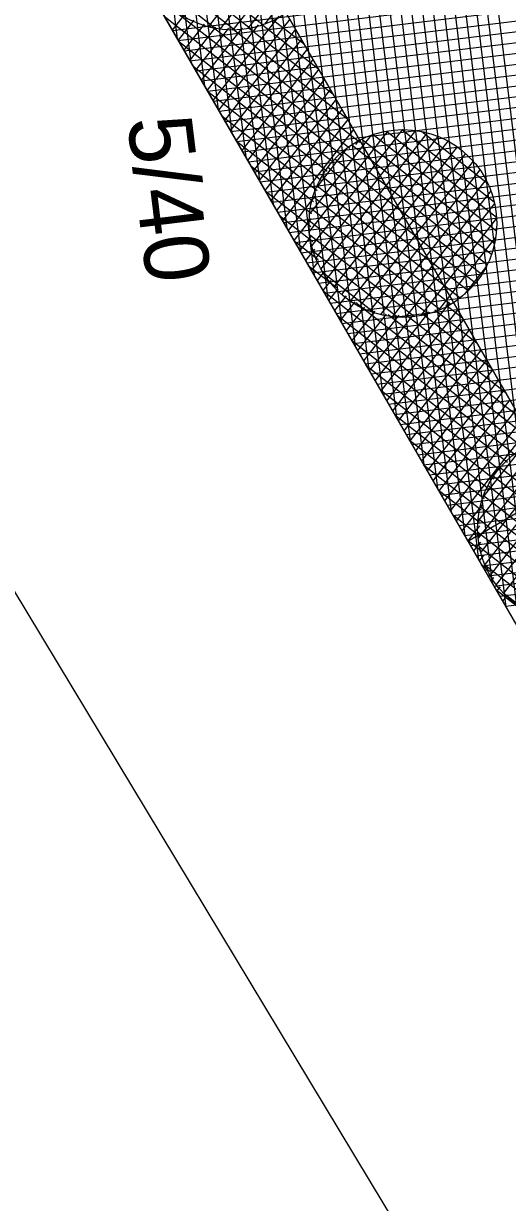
# Model space of a CAD drawing. Extents: x -566982 to -566809, y -1095912 to -1095685.
# Drawn here: x -566913.58 to -566904.55, y -1095817.35 to -1095795.39 of the extents above; entities that cross this region are included whole.
import ezdxf

# ---------------------------------------------------------------- set-up
doc = ezdxf.new("R2010")
doc.units = 0
for name, color, linetype in [('Vrstva 1', 7, 'Continuous'), ('Vrstva 40', 7, 'Continuous'), ('Vrstva 41', 7, 'Continuous'), ('Vrstva 42', 7, 'Continuous'), ('Vrstva 43', 7, 'Continuous'), ('Vrstva 44', 7, 'Continuous')]:
    doc.layers.add(name, color=color, linetype=linetype)

msp = doc.modelspace()

# ---------------------------------------------------------------- linework, layer by layer
at = {"layer": 'Vrstva 1'}
for p, q in [((-566956.66, -1095716.28), (-566892.27, -1095827.53)), ((-566928.71, -1095781.18), (-566901.69, -1095825.95))]:
    msp.add_line(p, q, dxfattribs=at)
at = {"layer": 'Vrstva 41'}
for p, q in [((-566911.222, -1095794.786), (-566907.49, -1095797.706)), ((-566910.953, -1095795.25), (-566907.651, -1095797.834)), ((-566910.581, -1095795.226), (-566910.803, -1095795.51)), ((-566908.819, -1095795.246), (-566910.047, -1095796.816)), ((-566908.611, -1095795.304), (-566909.939, -1095797.002)), ((-566910.402, -1095795.322), (-566910.695, -1095795.696)), ((-566910.208, -1095795.398), (-566910.587, -1095795.883)), ((-566909.995, -1095795.451), (-566910.479, -1095796.069)), ((-566909.758, -1095795.473), (-566910.371, -1095796.256)), ((-566909.501, -1095795.468), (-566910.263, -1095796.442)), ((-566909.2, -1095795.408), (-566910.155, -1095796.629)), ((-566910.067, -1095795.435), (-566907.307, -1095797.595)), ((-566908.503, -1095795.491), (-566909.831, -1095797.189)), ((-566909.696, -1095795.472), (-566907.535, -1095797.163)), ((-566909.395, -1095795.453), (-566907.804, -1095796.698)), ((-566909.147, -1095795.393), (-566908.073, -1095796.234)), ((-566908.933, -1095795.307), (-566908.341, -1095795.77)), ((-566910.685, -1095795.714), (-566907.793, -1095797.976)), ((-566908.395, -1095795.678), (-566909.723, -1095797.375)), ((-566908.287, -1095795.864), (-566909.615, -1095797.562)), ((-566910.416, -1095796.178), (-566907.916, -1095798.135)), ((-566908.179, -1095796.051), (-566909.507, -1095797.748)), ((-566908.071, -1095796.237), (-566909.399, -1095797.935)), ((-566907.963, -1095796.424), (-566909.291, -1095798.121)), ((-566907.855, -1095796.61), (-566909.183, -1095798.308)), ((-566910.147, -1095796.642), (-566908.02, -1095798.307)), ((-566907.747, -1095796.797), (-566909.075, -1095798.495)), ((-566907.639, -1095796.983), (-566908.967, -1095798.681)), ((-566909.879, -1095797.106), (-566908.104, -1095798.495)), ((-566907.531, -1095797.17), (-566908.859, -1095798.868)), ((-566907.423, -1095797.357), (-566908.751, -1095799.054)), ((-566909.61, -1095797.571), (-566908.168, -1095798.699)), ((-566907.315, -1095797.543), (-566907.39, -1095797.639)), ((-566909.341, -1095798.035), (-566908.209, -1095798.921)), ((-566909.073, -1095798.499), (-566908.218, -1095799.168)), ((-566908.143, -1095798.601), (-566908.643, -1095799.241)), ((-566908.804, -1095798.963), (-566908.185, -1095799.447)), ((-566908.216, -1095799.019), (-566908.535, -1095799.427)), ((-566908.535, -1095799.427), (-566908.081, -1095799.783)), ((-566908.206, -1095799.331), (-566908.427, -1095799.614)), ((-566908.151, -1095799.586), (-566908.319, -1095799.8)), ((-566908.267, -1095799.891), (-566907.722, -1095800.318)), ((-566908.071, -1095799.808), (-566908.212, -1095799.987)), ((-566907.97, -1095800.003), (-566908.104, -1095800.174)), ((-566907.998, -1095800.356), (-566904.226, -1095803.307)), ((-566907.85, -1095800.174), (-566907.996, -1095800.36)), ((-566907.714, -1095800.325), (-566907.888, -1095800.547)), ((-566907.564, -1095800.458), (-566907.78, -1095800.733)), ((-566907.4, -1095800.572), (-566907.672, -1095800.92)), ((-566907.221, -1095800.669), (-566907.564, -1095801.106)), ((-566907.027, -1095800.745), (-566907.456, -1095801.293)), ((-566907.384, -1095800.583), (-566904.043, -1095803.197)), ((-566906.02, -1095800.756), (-566907.024, -1095802.039)), ((-566905.639, -1095800.593), (-566906.916, -1095802.226)), ((-566905.479, -1095800.714), (-566906.808, -1095802.412)), ((-566906.146, -1095800.789), (-566904.849, -1095801.804)), ((-566905.909, -1095800.72), (-566905.117, -1095801.34)), ((-566905.703, -1095800.628), (-566905.386, -1095800.876)), ((-566907.73, -1095800.82), (-566904.401, -1095803.424)), ((-566906.815, -1095800.798), (-566907.348, -1095801.479)), ((-566906.578, -1095800.82), (-566907.24, -1095801.666)), ((-566906.32, -1095800.815), (-566907.132, -1095801.853)), ((-566906.776, -1095800.804), (-566904.311, -1095802.733)), ((-566905.371, -1095800.901), (-566906.7, -1095802.599)), ((-566906.434, -1095800.817), (-566904.58, -1095802.268)), ((-566905.263, -1095801.088), (-566906.592, -1095802.785)), ((-566907.461, -1095801.284), (-566904.555, -1095803.557)), ((-566905.155, -1095801.274), (-566906.484, -1095802.972)), ((-566905.047, -1095801.461), (-566906.376, -1095803.158)), ((-566904.94, -1095801.647), (-566906.268, -1095803.345)), ((-566907.192, -1095801.748), (-566904.691, -1095803.706)), ((-566904.832, -1095801.834), (-566906.16, -1095803.532)), ((-566904.724, -1095802.02), (-566906.052, -1095803.718)), ((-566906.924, -1095802.212), (-566904.808, -1095803.868)), ((-566904.616, -1095802.207), (-566905.944, -1095803.905)), ((-566904.508, -1095802.393), (-566905.836, -1095804.091)), ((-566906.655, -1095802.676), (-566904.906, -1095804.045)), ((-566904.4, -1095802.58), (-566905.728, -1095804.278)), ((-566904.292, -1095802.767), (-566905.62, -1095804.464)), ((-566904.184, -1095802.953), (-566905.512, -1095804.651)), ((-566906.386, -1095803.141), (-566904.986, -1095804.236)), ((-566906.118, -1095803.605), (-566905.044, -1095804.445)), ((-566905.849, -1095804.069), (-566905.075, -1095804.674)), ((-566905.02, -1095804.346), (-566905.404, -1095804.837)), ((-566905.58, -1095804.533), (-566905.073, -1095804.93)), ((-566905.077, -1095804.744), (-566905.296, -1095805.024)), ((-566905.312, -1095804.997), (-566905.024, -1095805.222)), ((-566905.06, -1095805.047), (-566905.188, -1095805.211)), ((-566905.002, -1095805.297), (-566905.08, -1095805.397)), ((-566905.043, -1095805.461), (-566904.883, -1095805.586)), ((-566904.92, -1095805.517), (-566904.972, -1095805.584)), ((-566904.815, -1095805.707), (-566904.864, -1095805.77)), ((-566904.774, -1095805.926), (-566901.554, -1095808.446)), ((-566904.693, -1095805.876), (-566904.756, -1095805.957)), ((-566904.556, -1095806.025), (-566904.648, -1095806.143))]:
    msp.add_line(p, q, dxfattribs=at)
at = {"layer": 'Vrstva 42'}
msp.add_line((-566905.294, -1095805.027), (-566903.563, -1095804.025), dxfattribs=at)
msp.add_lwpolyline([(-566834.15, -1095760.69), (-566836.072, -1095760.136), (-566841.286, -1095779.189), (-566855.268, -1095796.126), (-566881.984, -1095814.851), (-566891.818, -1095824.318), (-566954.342, -1095716.292), (-566956.66, -1095716.28), (-566892.27, -1095827.53), (-566880.71, -1095816.4), (-566853.9, -1095797.61), (-566839.47, -1095780.13)], close=True, dxfattribs=at)
at = {"layer": 'Vrstva 43'}
for p, q in [((-566913.798, -1095770.37), (-566910.711, -1095795.668)), ((-566913.543, -1095770.811), (-566910.456, -1095796.109)), ((-566913.288, -1095771.252), (-566910.2, -1095796.551)), ((-566913.032, -1095771.693), (-566909.945, -1095796.992)), ((-566912.777, -1095772.134), (-566909.69, -1095797.433)), ((-566912.522, -1095772.575), (-566909.435, -1095797.874)), ((-566912.266, -1095773.016), (-566909.179, -1095798.315)), ((-566912.011, -1095773.458), (-566908.924, -1095798.756)), ((-566911.756, -1095773.899), (-566908.669, -1095799.197)), ((-566911.5, -1095774.34), (-566908.413, -1095799.638)), ((-566911.245, -1095774.781), (-566908.158, -1095800.08)), ((-566910.99, -1095775.222), (-566907.903, -1095800.521)), ((-566910.735, -1095775.663), (-566907.647, -1095800.962)), ((-566910.479, -1095776.104), (-566907.392, -1095801.403)), ((-566910.224, -1095776.545), (-566907.137, -1095801.844)), ((-566909.969, -1095776.986), (-566906.881, -1095802.285)), ((-566909.713, -1095777.428), (-566906.626, -1095802.726)), ((-566909.458, -1095777.869), (-566906.371, -1095803.167)), ((-566909.203, -1095778.31), (-566906.115, -1095803.608)), ((-566908.947, -1095778.751), (-566905.86, -1095804.05)), ((-566908.692, -1095779.192), (-566905.605, -1095804.491)), ((-566908.437, -1095779.633), (-566905.35, -1095804.932)), ((-566908.181, -1095780.074), (-566905.094, -1095805.373)), ((-566907.926, -1095780.515), (-566904.839, -1095805.814)), ((-566907.671, -1095780.957), (-566904.584, -1095806.255)), ((-566907.415, -1095781.398), (-566904.328, -1095806.696)), ((-566907.16, -1095781.839), (-566904.073, -1095807.137)), ((-566906.905, -1095782.28), (-566903.818, -1095807.579)), ((-566906.65, -1095782.721), (-566903.562, -1095808.02)), ((-566906.394, -1095783.162), (-566903.307, -1095808.461)), ((-566906.139, -1095783.603), (-566903.052, -1095808.902)), ((-566910.8, -1095795.514), (-566900.007, -1095794.197)), ((-566910.691, -1095795.703), (-566899.898, -1095794.385)), ((-566910.582, -1095795.891), (-566899.789, -1095794.574)), ((-566910.473, -1095796.079), (-566899.68, -1095794.762)), ((-566910.365, -1095796.267), (-566899.572, -1095794.95)), ((-566910.256, -1095796.455), (-566899.463, -1095795.138)), ((-566910.147, -1095796.643), (-566899.354, -1095795.326)), ((-566910.038, -1095796.832), (-566899.245, -1095795.515)), ((-566909.929, -1095797.02), (-566899.136, -1095795.703)), ((-566909.82, -1095797.208), (-566899.027, -1095795.891)), ((-566909.711, -1095797.396), (-566898.918, -1095796.079)), ((-566909.602, -1095797.584), (-566898.809, -1095796.267)), ((-566909.493, -1095797.773), (-566898.7, -1095796.456)), ((-566909.384, -1095797.961), (-566898.591, -1095796.644)), ((-566909.275, -1095798.149), (-566898.482, -1095796.832)), ((-566909.166, -1095798.337), (-566898.373, -1095797.02)), ((-566909.057, -1095798.525), (-566898.264, -1095797.208)), ((-566908.949, -1095798.714), (-566898.156, -1095797.396)), ((-566908.84, -1095798.902), (-566898.047, -1095797.585)), ((-566908.731, -1095799.09), (-566897.938, -1095797.773)), ((-566908.622, -1095799.278), (-566897.829, -1095797.961)), ((-566908.513, -1095799.466), (-566897.72, -1095798.149)), ((-566908.404, -1095799.655), (-566897.611, -1095798.337)), ((-566908.295, -1095799.843), (-566897.502, -1095798.526)), ((-566908.186, -1095800.031), (-566897.393, -1095798.714)), ((-566908.077, -1095800.219), (-566897.284, -1095798.902)), ((-566907.968, -1095800.407), (-566897.175, -1095799.09)), ((-566907.859, -1095800.595), (-566897.066, -1095799.278)), ((-566907.75, -1095800.784), (-566896.957, -1095799.467)), ((-566907.641, -1095800.972), (-566896.848, -1095799.655)), ((-566907.533, -1095801.16), (-566896.74, -1095799.843)), ((-566907.424, -1095801.348), (-566896.631, -1095800.031)), ((-566907.315, -1095801.536), (-566896.522, -1095800.219)), ((-566907.206, -1095801.725), (-566896.413, -1095800.408)), ((-566907.097, -1095801.913), (-566896.304, -1095800.596)), ((-566906.988, -1095802.101), (-566896.195, -1095800.784)), ((-566906.879, -1095802.289), (-566896.086, -1095800.972)), ((-566906.77, -1095802.477), (-566895.977, -1095801.16)), ((-566906.661, -1095802.666), (-566895.868, -1095801.349)), ((-566906.552, -1095802.854), (-566895.759, -1095801.537)), ((-566906.443, -1095803.042), (-566895.65, -1095801.725)), ((-566906.334, -1095803.23), (-566895.541, -1095801.913)), ((-566906.225, -1095803.418), (-566895.432, -1095802.101)), ((-566906.117, -1095803.607), (-566895.324, -1095802.289)), ((-566906.008, -1095803.795), (-566895.215, -1095802.478)), ((-566905.899, -1095803.983), (-566895.106, -1095802.666)), ((-566905.79, -1095804.171), (-566894.997, -1095802.854)), ((-566905.681, -1095804.359), (-566894.888, -1095803.042)), ((-566905.572, -1095804.548), (-566894.779, -1095803.23)), ((-566905.463, -1095804.736), (-566894.67, -1095803.419)), ((-566905.354, -1095804.924), (-566894.561, -1095803.607)), ((-566905.245, -1095805.112), (-566894.452, -1095803.795)), ((-566905.136, -1095805.3), (-566894.343, -1095803.983)), ((-566905.027, -1095805.488), (-566894.234, -1095804.171)), ((-566904.918, -1095805.677), (-566894.125, -1095804.36)), ((-566904.809, -1095805.865), (-566894.016, -1095804.548)), ((-566904.701, -1095806.053), (-566893.908, -1095804.736)), ((-566904.592, -1095806.241), (-566893.799, -1095804.924))]:
    msp.add_line(p, q, dxfattribs=at)
msp.add_lwpolyline([(-566834.15, -1095760.69), (-566843.76, -1095757.92), (-566848.55, -1095775.42), (-566860.75, -1095790.2), (-566887.09, -1095808.66), (-566890.01, -1095811.47), (-566945.07, -1095716.34), (-566956.66, -1095716.28), (-566892.27, -1095827.53), (-566880.71, -1095816.4), (-566853.9, -1095797.61), (-566839.47, -1095780.13)], close=True, dxfattribs=at)
at = {"layer": 'Vrstva 44'}
for p, q in [((-566908.152, -1095792.912), (-566910.136, -1095795.446)), ((-566908.058, -1095793.116), (-566909.916, -1095795.49)), ((-566907.985, -1095793.347), (-566909.673, -1095795.504)), ((-566911.426, -1095793.594), (-566909.109, -1095795.407)), ((-566907.943, -1095793.618), (-566909.403, -1095795.483)), ((-566911.432, -1095793.843), (-566909.35, -1095795.472)), ((-566907.948, -1095793.949), (-566909.083, -1095795.399)), ((-566911.394, -1095794.127), (-566909.635, -1095795.504)), ((-566911.284, -1095794.467), (-566909.994, -1095795.477)), ((-566906.784, -1095797.384), (-566908.245, -1095799.252)), ((-566907.103, -1095797.468), (-566908.241, -1095798.922)), ((-566906.512, -1095797.362), (-566908.203, -1095799.523)), ((-566906.271, -1095797.377), (-566908.129, -1095799.752)), ((-566906.051, -1095797.422), (-566908.034, -1095799.956)), ((-566905.85, -1095797.488), (-566907.921, -1095800.135)), ((-566907.055, -1095797.452), (-566904.759, -1095799.248)), ((-566906.812, -1095797.388), (-566904.759, -1095798.995)), ((-566906.521, -1095797.362), (-566904.801, -1095798.708)), ((-566906.153, -1095797.396), (-566904.926, -1095798.356)), ((-566907.542, -1095797.703), (-566908.117, -1095798.438)), ((-566905.664, -1095797.575), (-566907.79, -1095800.293)), ((-566905.494, -1095797.683), (-566907.646, -1095800.433)), ((-566907.458, -1095797.645), (-566904.851, -1095799.684)), ((-566907.27, -1095797.538), (-566904.794, -1095799.475)), ((-566907.771, -1095797.907), (-566905.03, -1095800.052)), ((-566907.624, -1095797.769), (-566904.93, -1095799.877)), ((-566905.338, -1095797.808), (-566907.488, -1095800.555)), ((-566907.901, -1095798.06), (-566905.148, -1095800.214)), ((-566905.195, -1095797.95), (-566907.316, -1095800.66)), ((-566905.067, -1095798.111), (-566907.127, -1095800.744)), ((-566908.013, -1095798.226), (-566905.283, -1095800.362)), ((-566904.957, -1095798.294), (-566906.924, -1095800.808)), ((-566908.105, -1095798.408), (-566905.436, -1095800.496)), ((-566904.865, -1095798.501), (-566906.701, -1095800.848)), ((-566908.177, -1095798.606), (-566905.61, -1095800.614)), ((-566904.794, -1095798.735), (-566906.455, -1095800.858)), ((-566908.228, -1095798.82), (-566905.807, -1095800.714)), ((-566904.758, -1095799.013), (-566906.178, -1095800.828)), ((-566908.251, -1095799.056), (-566906.03, -1095800.794)), ((-566908.24, -1095799.319), (-566906.289, -1095800.845)), ((-566904.772, -1095799.357), (-566905.848, -1095800.731)), ((-566908.174, -1095799.623), (-566906.599, -1095800.856)), ((-566904.941, -1095799.898), (-566905.362, -1095800.435)), ((-566908, -1095800.014), (-566907.019, -1095800.782)), ((-566903.915, -1095803.134), (-566905.105, -1095804.654)), ((-566903.604, -1095803.06), (-566905.101, -1095804.973)), ((-566903.336, -1095803.042), (-566905.053, -1095805.236)), ((-566903.099, -1095803.063), (-566904.976, -1095805.463)), ((-566902.881, -1095803.11), (-566904.879, -1095805.663)), ((-566902.682, -1095803.179), (-566904.762, -1095805.838)), ((-566904.325, -1095803.332), (-566905.012, -1095804.211)), ((-566902.499, -1095803.271), (-566904.63, -1095805.994)), ((-566904.813, -1095803.816), (-566902.065, -1095805.966)), ((-566904.692, -1095803.657), (-566901.94, -1095805.81)), ((-566904.915, -1095803.99), (-566902.21, -1095806.107)), ((-566905, -1095804.178), (-566902.373, -1095806.233)), ((-566905.063, -1095804.383), (-566902.557, -1095806.343)), ((-566905.1, -1095804.607), (-566902.763, -1095806.436)), ((-566905.11, -1095804.853), (-566903.003, -1095806.502)), ((-566905.076, -1095805.134), (-566903.281, -1095806.538)), ((-566904.974, -1095805.467), (-566903.63, -1095806.519)), ((-566904.644, -1095805.98), (-566904.205, -1095806.323))]:
    msp.add_line(p, q, dxfattribs=at)
for centre in [(-566909.685, -1095793.756), (-566906.503, -1095799.11), (-566903.362, -1095804.792)]:
    msp.add_circle(centre, 1.75, dxfattribs=at)

# ---------------------------------------------------------------- texts
at = {"layer": 'Vrstva 40'}
msp.add_text('5/40', height=1.2, rotation=276.9575, dxfattribs=at).set_placement((-566911.646, -1095797.169))

doc.saveas('drawing.dxf')
